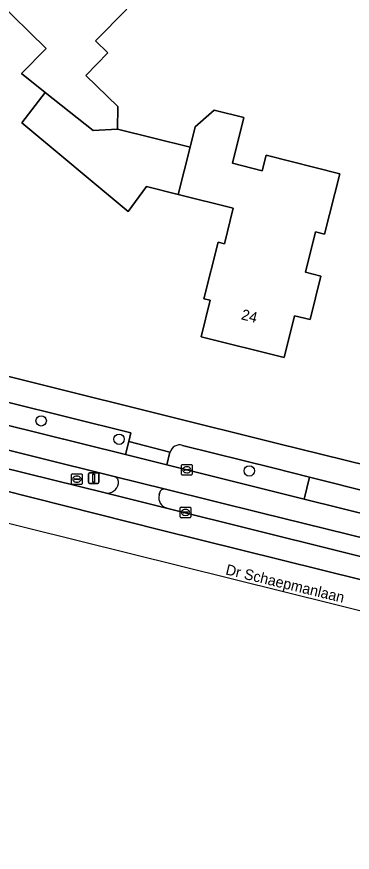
# Model space of a CAD drawing. Extents: x 161347 to 161881, y 382161 to 382804.
# Drawn here: x 161439.4 to 161471.1, y 382161.2 to 382240.1 of the extents above; entities that cross this region are included whole.
import ezdxf

# ---------------------------------------------------------------- set-up
doc = ezdxf.new("R2010")
doc.units = 0
for name, color, linetype in [('IMGEO_Berm_groen', 7, 'Continuous'), ('IMGEO_Boom', 7, 'Continuous'), ('IMGEO_Erf', 7, 'Continuous'), ('IMGEO_Fietspad_gesloten', 7, 'Continuous'), ('IMGEO_Kolk', 7, 'Continuous'), ('IMGEO_Lichtmast', 7, 'Continuous'), ('IMGEO_Openbare_ruimte_label', 7, 'Continuous'), ('IMGEO_Pand', 7, 'Continuous'), ('IMGEO_Pand_nummerreeks', 7, 'Continuous'), ('IMGEO_Parkeervlak_gesloten', 7, 'Continuous'), ('IMGEO_Rijbaan_lokaal_gesloten', 7, 'Continuous'), ('IMGEO_Rioolput', 7, 'Continuous'), ('IMGEO_Voetpad_open', 7, 'Continuous')]:
    doc.layers.add(name, color=color, linetype=linetype)

msp = doc.modelspace()

# ---------------------------------------------------------------- linework, layer by layer
at = {"layer": 'IMGEO_Berm_groen'}
for points in [[(161448.631, 382196.696), (161418.403, 382204.211)], [(161427.287, 382198.569), (161429.682, 382199.431), (161429.995, 382199.482), (161430.279, 382199.461), (161447.783, 382195.136)], [(161463.694, 382197.481), (161455.074, 382199.619)], [(161453.883, 382198.974), (161453.587, 382197.783), (161463.127, 382195.408), (161466.523, 382194.566), (161467.037, 382196.636), (161463.694, 382197.481)], [(161479.435, 382193.502), (161467.037, 382196.636), (161466.523, 382194.566), (161480.111, 382191.197), (161480.334, 382192.164), (161480.435, 382192.564)], [(161462.581, 382193.233), (161453.454, 382195.498)], [(161452.897, 382195.117), (161452.854, 382194.921)], [(161453.562, 382193.718), (161477.906, 382187.637)], [(161478.779, 382189.246), (161462.581, 382193.233)]]:
    msp.add_lwpolyline(points, dxfattribs=at)
msp.add_lwpolyline([(161438.548, 382203.693), (161438.04, 382201.653), (161449.683, 382198.752), (161449.987, 382199.986), (161450.193, 382200.822)], close=True, dxfattribs=at)
for centre, radius, start, end in [((161454.782, 382198.737), 0.929, 71.66678, 165.20978), ((161448.445, 382196.132), 0.594, 348.61678, 71.73904), ((161447.948, 382196.222), 1.099, 261.37224, 349.11718), ((161453.359, 382195.039), 0.469, 78.36439, 170.38155), ((161453.83, 382194.686), 1.004, 166.44669, 254.50938)]:
    msp.add_arc(centre, radius, start, end, dxfattribs=at)
at = {"layer": 'IMGEO_Boom'}
for centre in [(161441.737, 382201.935), (161449.082, 382200.197), (161461.363, 382197.214)]:
    msp.add_circle(centre, 0.489, dxfattribs=at)
at = {"layer": 'IMGEO_Erf'}
for points in [[(161449.8, 382240.772), (161446.864, 382237.771), (161448.03, 382236.632), (161445.96, 382234.517), (161448.963, 382231.58), (161448.936, 382229.455), (161455.78, 382227.741), (161456.266, 382229.681), (161457.808, 382231.015), (161458.063, 382231.236), (161460.857, 382230.536), (161459.78, 382226.235), (161462.583, 382225.533), (161462.946, 382226.983), (161469.884, 382225.231), (161468.463, 382219.553), (161467.608, 382219.769), (161466.653, 382215.957), (161468.118, 382215.59), (161467.091, 382211.487), (161465.626, 382211.853), (161464.635, 382207.897), (161456.81, 382209.857), (161457.674, 382213.308), (161457.082, 382213.456), (161458.418, 382218.791), (161459.01, 382218.643), (161459.848, 382221.99), (161454.665, 382223.288), (161451.662, 382224.041), (161449.949, 382221.677), (161439.919, 382230.035), (161442.119, 382232.914), (161439.89, 382234.697), (161442.21, 382237.067), (161437.441, 382241.734)], [(161420.378, 382210.687), (161464.013, 382199.817), (161500, 382190.938), (161540.678, 382180.901)]]:
    msp.add_lwpolyline(points, dxfattribs=at)
at = {"layer": 'IMGEO_Fietspad_gesloten'}
for points in [[(161501.233, 382185.995), (161500, 382186.3), (161496.51, 382187.162), (161490.686, 382188.602), (161483.93, 382190.272), (161480.111, 382191.197), (161466.523, 382194.566), (161463.127, 382195.408), (161453.587, 382197.783), (161449.683, 382198.752), (161438.04, 382201.653), (161418.591, 382206.5), (161416.251, 382207.083), (161413.969, 382207.749), (161413.397, 382208.039), (161413.228, 382208.133), (161413.06, 382208.229), (161412.312, 382205.251)], [(161413.236, 382205.52), (161415.308, 382205.003), (161418.403, 382204.211), (161448.631, 382196.696), (161453.454, 382195.498), (161462.581, 382193.233), (161478.779, 382189.246), (161484.015, 382187.92), (161495.709, 382185.028), (161500, 382183.961), (161501.342, 382183.627), (161519.01, 382179.306), (161523.769, 382178.11), (161539.444, 382174.246), (161544.627, 382172.985), (161563.516, 382168.335), (161567.78, 382167.465), (161571.619, 382166.9), (161573.608, 382166.754), (161575.893, 382166.568), (161576.527, 382168.636), (161571.72, 382169.156)]]:
    msp.add_lwpolyline(points, dxfattribs=at)
at = {"layer": 'IMGEO_Kolk'}
for p, q in [((161454.971, 382196.894), (161454.971, 382197.746)), ((161455.046, 382197.82), (161455.898, 382197.82)), ((161455.972, 382197.746), (161455.972, 382196.894)), ((161455.23, 382197.314), (161455.23, 382197.326)), ((161455.668, 382197.277), (161455.27, 382197.277)), ((161455.273, 382197.363), (161455.671, 382197.363)), ((161455.482, 382197.04), (161455.457, 382197.04)), ((161455.459, 382197.6), (161455.484, 382197.6)), ((161455.714, 382197.326), (161455.714, 382197.314)), ((161455.898, 382196.82), (161455.046, 382196.82)), ((161454.847, 382192.872), (161454.847, 382193.724)), ((161454.922, 382193.798), (161455.774, 382193.798)), ((161455.848, 382193.724), (161455.848, 382192.872)), ((161455.106, 382193.292), (161455.106, 382193.304)), ((161455.544, 382193.255), (161455.146, 382193.255)), ((161455.149, 382193.341), (161455.547, 382193.341)), ((161455.358, 382193.018), (161455.333, 382193.018)), ((161455.335, 382193.578), (161455.36, 382193.578)), ((161455.59, 382193.304), (161455.59, 382193.292)), ((161455.774, 382192.798), (161454.922, 382192.798))]:
    msp.add_line(p, q, dxfattribs=at)
for points in [[(161454.971, 382196.894), (161454.971, 382197.746)], [(161455.046, 382197.82), (161455.898, 382197.82)], [(161455.972, 382197.746), (161455.972, 382196.894)], [(161455.898, 382196.82), (161455.046, 382196.82)], [(161454.847, 382192.872), (161454.847, 382193.724)], [(161454.922, 382193.798), (161455.774, 382193.798)], [(161455.848, 382193.724), (161455.848, 382192.872)], [(161455.774, 382192.798), (161454.922, 382192.798)]]:
    msp.add_lwpolyline(points, dxfattribs=at)
for centre, radius, start, end in [((161455.048, 382197.744), 0.0765, 91.55205, 178.44795), ((161455.048, 382197.744), 0.0765, 91.55205, 178.44795), ((161455.896, 382197.744), 0.0765, 1.55205, 88.44795), ((161455.896, 382197.744), 0.0765, 1.55205, 88.44795), ((161455.048, 382196.896), 0.0765, 181.55205, 268.44795), ((161455.048, 382196.896), 0.0765, 181.55205, 268.44795), ((161455.27, 382197.323), 0.0403, 85.87752, 175.75265), ((161455.267, 382197.313), 0.0366, 178.93798, 274.71019), ((161455.671, 382197.32), 0.043, 264.86636, 352.45326), ((161455.675, 382197.325), 0.0386, 1.73085, 96.63898), ((161455.896, 382196.896), 0.0765, 271.55205, 358.44795), ((161455.896, 382196.896), 0.0765, 271.55205, 358.44795), ((161454.924, 382193.722), 0.0765, 91.55205, 178.44795), ((161454.924, 382193.722), 0.0765, 91.55205, 178.44795), ((161455.772, 382193.722), 0.0765, 1.55205, 88.44795), ((161455.772, 382193.722), 0.0765, 1.55205, 88.44795), ((161455.146, 382193.301), 0.0403, 85.87752, 175.75265), ((161455.143, 382193.291), 0.0366, 178.93798, 274.71019), ((161455.547, 382193.298), 0.043, 264.86636, 352.45326), ((161455.551, 382193.303), 0.0386, 1.73085, 96.63898), ((161454.924, 382192.874), 0.0765, 181.55205, 268.44795), ((161454.924, 382192.874), 0.0765, 181.55205, 268.44795), ((161455.772, 382192.874), 0.0765, 271.55205, 358.44795), ((161455.772, 382192.874), 0.0765, 271.55205, 358.44795)]:
    msp.add_arc(centre, radius, start, end, dxfattribs=at)
for centre, major_axis, ratio, start_param, end_param in [((161455.458, 382197.32), (-0.387, 0.002), 0.722429, 4.712389, 7.853982), ((161455.483, 382197.32), (-0.39, 0.002), 0.717154, 1.570796, 4.712389), ((161455.334, 382193.298), (-0.387, 0.002), 0.722429, 4.712389, 7.853982), ((161455.359, 382193.298), (-0.39, 0.002), 0.717154, 1.570796, 4.712389)]:
    msp.add_ellipse(centre, major_axis=major_axis, ratio=ratio, start_param=start_param, end_param=end_param, dxfattribs=at)
at = {"layer": 'IMGEO_Lichtmast'}
for p, q in [((161446.188, 382196.143), (161446.188, 382196.943)), ((161446.188, 382196.943), (161446.188, 382196.143)), ((161446.288, 382197.043), (161447.078, 382197.043)), ((161447.078, 382197.043), (161446.288, 382197.043)), ((161447.178, 382196.943), (161447.178, 382196.143)), ((161447.178, 382196.143), (161447.178, 382196.943)), ((161447.078, 382196.043), (161446.288, 382196.043)), ((161446.288, 382196.043), (161447.078, 382196.043))]:
    msp.add_line(p, q, dxfattribs=at)
msp.add_lwpolyline([(161446.608, 382196.918), (161446.758, 382196.918), (161446.758, 382196.168), (161446.608, 382196.168), (161446.608, 382196.918)], dxfattribs=at)
for centre, start, end in [((161446.288, 382196.943), 90, 180), ((161446.288, 382196.943), 90, 180), ((161447.078, 382196.943), 0, 90), ((161447.078, 382196.943), 360, 90), ((161446.288, 382196.143), 180, 270), ((161446.288, 382196.143), 180, 270), ((161447.078, 382196.143), 270, 0), ((161447.078, 382196.143), 270, 0)]:
    msp.add_arc(centre, 0.1, start, end, dxfattribs=at)
at = {"layer": 'IMGEO_Pand'}
for points in [[(161442.119, 382232.914), (161446.641, 382229.335), (161448.936, 382229.455), (161448.963, 382231.58), (161445.96, 382234.517), (161448.03, 382236.632), (161446.864, 382237.771), (161449.8, 382240.772), (161441.188, 382249.2), (161440.835, 382248.84), (161440.343, 382249.322), (161438.55, 382247.491), (161438.994, 382247.056), (161435.79, 382243.781), (161437.657, 382241.954), (161437.441, 382241.734), (161442.21, 382237.067), (161439.89, 382234.697)], [(161442.119, 382232.914), (161439.919, 382230.035), (161449.949, 382221.677), (161451.662, 382224.041), (161454.665, 382223.288), (161455.78, 382227.741), (161448.936, 382229.455), (161446.641, 382229.335)], [(161469.884, 382225.231), (161462.946, 382226.983), (161462.583, 382225.533), (161459.78, 382226.235), (161460.857, 382230.536), (161458.063, 382231.236), (161457.808, 382231.015), (161456.266, 382229.681), (161455.78, 382227.741), (161454.665, 382223.288), (161459.848, 382221.99), (161459.01, 382218.643), (161458.418, 382218.791), (161457.082, 382213.456), (161457.674, 382213.308), (161456.81, 382209.857), (161464.635, 382207.897), (161465.626, 382211.853), (161467.091, 382211.487), (161468.118, 382215.59), (161466.653, 382215.957), (161467.608, 382219.769), (161468.463, 382219.553)]]:
    msp.add_lwpolyline(points, close=True, dxfattribs=at)
at = {"layer": 'IMGEO_Parkeervlak_gesloten'}
for points in [[(161571.104, 382164.701), (161570.133, 382165.693), (161563.09, 382166.989), (161562.741, 382167.053), (161553.68, 382168.99), (161544.683, 382171.197), (161538.439, 382172.703), (161523.782, 382176.315), (161518.095, 382177.712), (161501.466, 382181.829), (161500, 382182.195), (161494.84, 382183.482), (161484.029, 382186.14), (161477.906, 382187.637), (161453.562, 382193.718), (161447.783, 382195.136), (161430.279, 382199.461), (161429.995, 382199.482), (161429.682, 382199.431), (161427.287, 382198.569)], [(161425.904, 382198.493), (161453.047, 382191.62), (161517.576, 382175.615), (161553.188, 382166.887), (161562.35, 382164.929)]]:
    msp.add_lwpolyline(points, dxfattribs=at)
at = {"layer": 'IMGEO_Rijbaan_lokaal_gesloten'}
for points in [[(161562.35, 382164.929), (161553.188, 382166.887), (161517.576, 382175.615), (161453.047, 382191.62), (161425.904, 382198.493)], [(161415.973, 382197.911), (161562.018, 382161.64), (161575.538, 382161.247)]]:
    msp.add_lwpolyline(points, dxfattribs=at)
at = {"layer": 'IMGEO_Rioolput'}
for p, q in [((161444.681, 382196.938), (161445.533, 382196.938)), ((161444.606, 382196.012), (161444.606, 382196.864)), ((161444.865, 382196.432), (161444.865, 382196.444)), ((161445.303, 382196.395), (161444.905, 382196.395)), ((161444.908, 382196.481), (161445.306, 382196.481)), ((161445.117, 382196.158), (161445.092, 382196.158)), ((161445.094, 382196.718), (161445.119, 382196.718)), ((161445.349, 382196.444), (161445.349, 382196.432)), ((161445.607, 382196.864), (161445.607, 382196.012)), ((161445.533, 382195.938), (161444.681, 382195.938))]:
    msp.add_line(p, q, dxfattribs=at)
for points in [[(161444.681, 382196.938), (161445.533, 382196.938)], [(161444.606, 382196.012), (161444.606, 382196.864)], [(161445.607, 382196.864), (161445.607, 382196.012)], [(161445.533, 382195.938), (161444.681, 382195.938)]]:
    msp.add_lwpolyline(points, dxfattribs=at)
for centre, radius, start, end in [((161444.683, 382196.862), 0.0765, 91.55205, 178.44795), ((161444.683, 382196.862), 0.0765, 91.55205, 178.44795), ((161445.531, 382196.862), 0.0765, 1.55205, 88.44795), ((161445.531, 382196.862), 0.0765, 1.55205, 88.44795), ((161444.905, 382196.441), 0.0403, 85.87752, 175.75265), ((161444.902, 382196.431), 0.0366, 178.93798, 274.71019), ((161445.306, 382196.438), 0.043, 264.86636, 352.45326), ((161445.31, 382196.443), 0.0386, 1.73085, 96.63898), ((161444.683, 382196.014), 0.0765, 181.55205, 268.44795), ((161444.683, 382196.014), 0.0765, 181.55205, 268.44795), ((161445.531, 382196.014), 0.0765, 271.55205, 358.44795), ((161445.531, 382196.014), 0.0765, 271.55205, 358.44795)]:
    msp.add_arc(centre, radius, start, end, dxfattribs=at)
for centre, major_axis, ratio, start_param, end_param in [((161445.093, 382196.438), (-0.387, 0.002), 0.722429, 4.712389, 7.853982), ((161445.118, 382196.438), (-0.39, 0.002), 0.717154, 1.570796, 4.712389)]:
    msp.add_ellipse(centre, major_axis=major_axis, ratio=ratio, start_param=start_param, end_param=end_param, dxfattribs=at)
at = {"layer": 'IMGEO_Voetpad_open'}
for points in [[(161464.013, 382199.817), (161420.378, 382210.687)], [(161420.081, 382208.245), (161438.548, 382203.693), (161450.193, 382200.822), (161449.987, 382199.986), (161453.883, 382198.974)], [(161455.074, 382199.619), (161463.694, 382197.481), (161467.037, 382196.636), (161479.435, 382193.502)], [(161540.678, 382180.901), (161500, 382190.938), (161464.013, 382199.817)], [(161453.454, 382195.498), (161448.631, 382196.696)], [(161447.783, 382195.136), (161453.562, 382193.718)], [(161452.854, 382194.921), (161452.897, 382195.117)]]:
    msp.add_lwpolyline(points, dxfattribs=at)
msp.add_lwpolyline([(161449.987, 382199.986), (161449.683, 382198.752), (161453.587, 382197.783), (161453.883, 382198.974)], close=True, dxfattribs=at)
for centre, radius, start, end in [((161454.782, 382198.737), 0.929, 71.66678, 165.20978), ((161448.445, 382196.132), 0.594, 348.61678, 71.73904), ((161447.948, 382196.222), 1.099, 261.37224, 349.11718), ((161453.359, 382195.039), 0.469, 78.36439, 170.38155), ((161453.83, 382194.686), 1.004, 166.44669, 254.50938)]:
    msp.add_arc(centre, radius, start, end, dxfattribs=at)

# ---------------------------------------------------------------- texts
at = {"layer": 'IMGEO_Openbare_ruimte_label'}
msp.add_text('Dr Schaepmanlaan', height=1, rotation=346.35276, dxfattribs=at).set_placement((161459.063, 382187.467))
at = {"layer": 'IMGEO_Pand_nummerreeks'}
msp.add_text('24', height=1, rotation=345.93962, dxfattribs=at).set_placement((161460.533, 382211.522))

doc.saveas('drawing.dxf')
